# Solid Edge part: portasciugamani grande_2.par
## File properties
Last saved by: i.fialdini
Revision: 62
Tipo di contenuto documento: 0
Accuracy: 0.990
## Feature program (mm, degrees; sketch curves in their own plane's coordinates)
body "unnamed Body 1"
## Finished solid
Body 1: solid body, 8 faces, 8 edges, 0 vertices.
  Faces by surface: cylinder 4, torus 4
  Edges by curve: circle 8
Bounding box of the edges (mm; curved faces can reach further): 715.000 x 507.500 x 21.000, from (-355.5, -222, -167.5) to (359.5, 285.5, -146.5).
Cylindrical faces by radius (mm): R10.5 x4
Toroidal faces (ring radius, tube radius in mm): R35 r10.5 x4
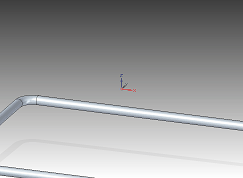
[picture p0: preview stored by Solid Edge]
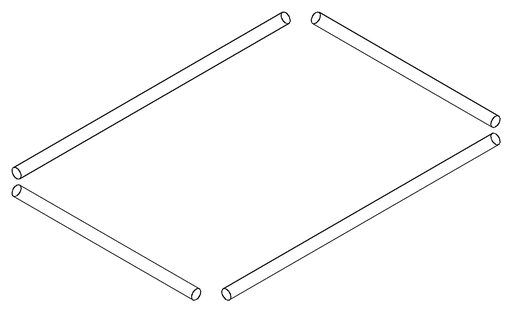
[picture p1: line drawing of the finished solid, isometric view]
